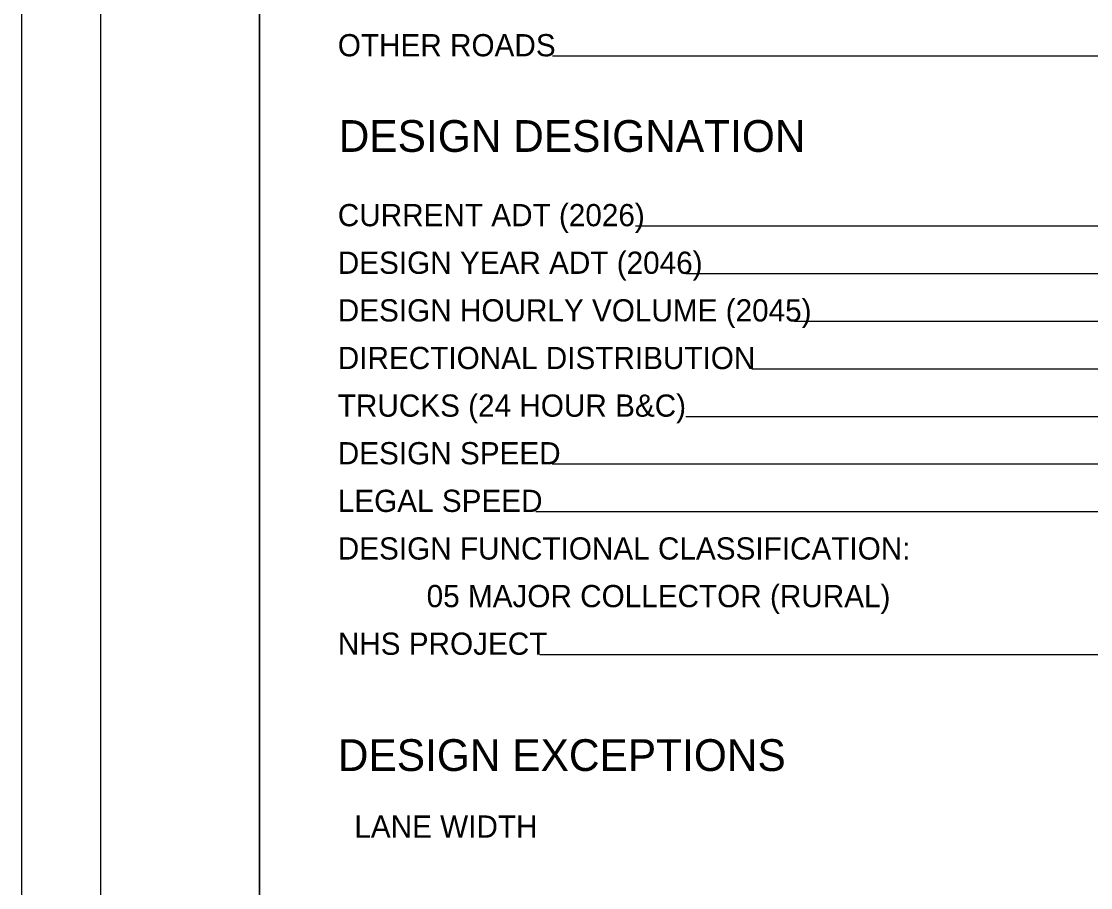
# Model space of a CAD drawing. Extents: x 0 to 48.6, y 0 to 22.
# Drawn here: x 0 to 6.74, y 5.64 to 11.1 of the extents above; entities that cross this region are included whole.
import ezdxf

# ---------------------------------------------------------------- set-up
doc = ezdxf.new("R2010")
doc.units = 0
for name, color, linetype in [('SH_Border', 7, 'Continuous'), ('SH_Cut_Line', 7, 'Continuous'), ('SH_Data', 7, 'Continuous'), ('SH_Text', 7, 'Continuous')]:
    doc.layers.add(name, color=color, linetype=linetype)

msp = doc.modelspace()

# ---------------------------------------------------------------- linework, layer by layer
at = {"layer": 'SH_Border'}
for points in [[(0.5, 21.5), (1.5, 21.5), (1.5, 0.5), (0.5, 0.5)], [(1.5, 21.5), (33.5, 21.5), (33.5, 0.5), (1.5, 0.5)]]:
    msp.add_lwpolyline(points, close=True, dxfattribs=at)
at = {"layer": 'SH_Cut_Line'}
msp.add_lwpolyline([(0, 0), (34, 0), (34, 22), (0, 22)], close=True, dxfattribs=at)
at = {"layer": 'SH_Data'}
for p, q in [((7.7, 10.8767), (3.3471, 10.8767)), ((7.6424, 9.8062), (3.871, 9.8062)), ((7.6368, 9.5062), (4.1885, 9.5062)), ((7.6368, 9.2062), (4.8723, 9.2062)), ((7.6368, 8.9062), (4.6037, 8.9062)), ((7.6368, 8.6062), (4.1885, 8.6062)), ((7.6368, 8.3062), (3.346, 8.3062)), ((7.6368, 8.0062), (3.2422, 8.0062)), ((7.6368, 7.1062), (3.2669, 7.1062))]:
    msp.add_line(p, q, dxfattribs=at)

# ---------------------------------------------------------------- texts
msp.add_text('DESIGN DESIGNATION', height=0.2, dxfattribs=at).set_placement((2, 10.2747))
at = {"layer": 'SH_Text'}
for s, height, p in [('OTHER ROADS', 0.14, (1.9944, 10.8767)), ('CURRENT ADT (2026)', 0.14, (1.9944, 9.8062)), ('DESIGN YEAR ADT (2046)', 0.14, (1.9944, 9.5062)), ('DESIGN HOURLY VOLUME (2045)', 0.14, (1.9944, 9.2062)), ('DIRECTIONAL DISTRIBUTION', 0.14, (1.9944, 8.9062)), ('TRUCKS (24 HOUR B&C)', 0.14, (1.9944, 8.6062)), ('DESIGN SPEED', 0.14, (1.9944, 8.3062)), ('LEGAL SPEED', 0.14, (1.9944, 8.0062)), ('DESIGN FUNCTIONAL CLASSIFICATION: ', 0.14, (1.9944, 7.7062)), ('05 MAJOR COLLECTOR (RURAL)                      ', 0.14, (2.5544, 7.4062)), ('NHS PROJECT', 0.14, (1.9944, 7.1062)), ('DESIGN EXCEPTIONS', 0.2, (1.9944, 6.3744)), ('  LANE WIDTH                             ', 0.14, (1.9944, 5.9544))]:
    msp.add_text(s, height=height, dxfattribs=at).set_placement(p)

doc.saveas('drawing.dxf')
